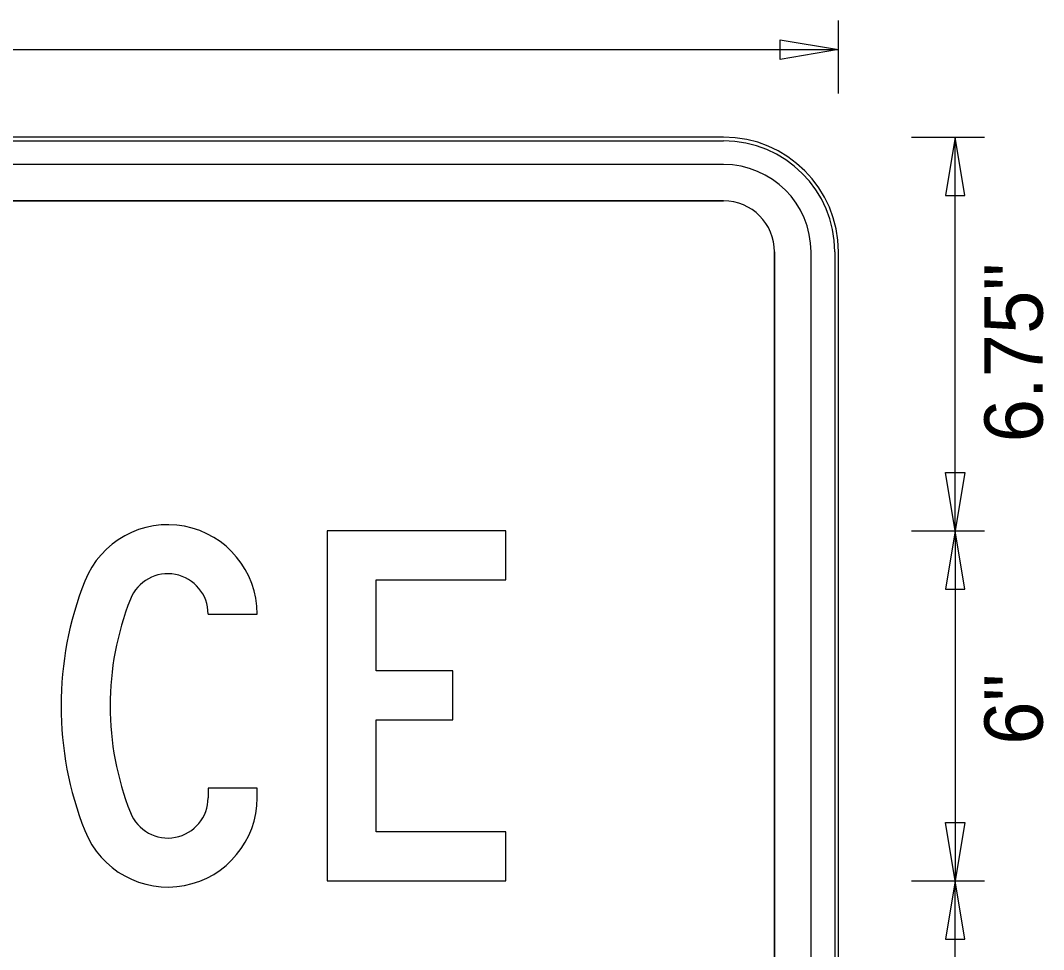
# Model space of a CAD drawing. Extents: x 1775472.9 to 1775494.7, y 1032415.7 to 1032420.8.
# Drawn here: x 1775475.339 to 1775477.092, y 1032418.237 to 1032419.83 of the extents above; entities that cross this region are included whole.
import ezdxf

# ---------------------------------------------------------------- set-up
doc = ezdxf.new("R2010")
doc.units = 0
for name, color, linetype in [('Default', 7, 'Continuous'), ('GSBWFILL', 7, 'Continuous'), ('GSCOLORFILL', 7, 'Continuous'), ('GSOUTLINE', 7, 'Continuous')]:
    doc.layers.add(name, color=color, linetype=linetype)

msp = doc.modelspace()

# ---------------------------------------------------------------- linework, layer by layer
at = {"layer": 'Default'}
for p, q in [((1775476.7401, 1032419.7052), (1775476.7401, 1032419.8302)), ((1775473.7401, 1032419.7802), (1775476.7401, 1032419.7802)), ((1775476.7401, 1032419.7052), (1775476.7401, 1032419.7052)), ((1775476.8651, 1032419.6302), (1775476.9901, 1032419.6302)), ((1775476.8651, 1032419.6302), (1775476.8651, 1032419.6302)), ((1775476.9401, 1032418.9552), (1775476.9401, 1032419.6302)), ((1775476.8651, 1032418.9552), (1775476.9901, 1032418.9552)), ((1775476.8651, 1032418.9552), (1775476.9901, 1032418.9552)), ((1775476.9401, 1032418.9552), (1775476.9401, 1032418.3552)), ((1775476.8651, 1032418.3552), (1775476.9901, 1032418.3552)), ((1775476.8651, 1032418.3552), (1775476.9901, 1032418.3552)), ((1775476.9401, 1032417.9052), (1775476.9401, 1032418.3552))]:
    msp.add_line(p, q, dxfattribs=at)
for points in [[(1775476.7401, 1032419.7802), (1775476.6401, 1032419.7635), (1775476.6401, 1032419.7969)], [(1775476.9401, 1032419.6302), (1775476.9234, 1032419.5302), (1775476.9568, 1032419.5302)], [(1775476.9401, 1032418.9552), (1775476.9234, 1032419.0552), (1775476.9568, 1032419.0552)], [(1775476.9401, 1032418.9552), (1775476.9234, 1032418.8552), (1775476.9568, 1032418.8552)], [(1775476.9401, 1032418.3552), (1775476.9234, 1032418.4552), (1775476.9568, 1032418.4552)], [(1775476.9401, 1032418.3552), (1775476.9234, 1032418.2552), (1775476.9568, 1032418.2552)]]:
    msp.add_lwpolyline(points, close=True, dxfattribs=at)
at = {"layer": 'GSBWFILL'}
for p, q in [((1775476.5432, 1032419.6302), (1775473.937, 1032419.6302)), ((1775476.5432, 1032419.5833), (1775473.937, 1032419.5833)), ((1775473.937, 1032419.5208), (1775476.5432, 1032419.5208)), ((1775476.6307, 1032419.4333), (1775476.6307, 1032416.8271)), ((1775476.6932, 1032416.8271), (1775476.6932, 1032419.4333)), ((1775476.7401, 1032416.8271), (1775476.7401, 1032419.4333)), ((1775475.6601, 1032418.8127), (1775475.7441, 1032418.8127))]:
    msp.add_line(p, q, dxfattribs=at)
msp.add_lwpolyline([(1775475.9481, 1032418.4392), (1775475.9481, 1032418.6312), (1775476.0795, 1032418.6312), (1775476.0795, 1032418.7152), (1775475.9481, 1032418.7152), (1775475.9481, 1032418.8712), (1775476.1701, 1032418.8712), (1775476.1701, 1032418.9552), (1775475.8641, 1032418.9552), (1775475.8641, 1032418.3552), (1775476.1701, 1032418.3552), (1775476.1701, 1032418.4392)], close=True, dxfattribs=at)
msp.add_lwpolyline([(1775475.7441, 1032418.4977), (1775475.7441, 1032418.5142), (1775475.6601, 1032418.5142), (1775475.6601, 1032418.4977)], dxfattribs=at)
for centre, radius, start, end in [((1775476.5432, 1032419.4333), 0.1969, 0, 90), ((1775476.5432, 1032419.4333), 0.15, 0, 90), ((1775476.5432, 1032419.4333), 0.0875, 0, 90), ((1775475.5911, 1032418.8127), 0.153, 0, 158.4314), ((1775475.9895, 1032418.6552), 0.5814, 158.4314, 201.5686), ((1775475.5911, 1032418.8127), 0.069, 0, 158.4314), ((1775475.9895, 1032418.6552), 0.4974, 158.4314, 201.5686), ((1775475.5911, 1032418.4977), 0.153, 201.5686, 0), ((1775475.5911, 1032418.4977), 0.069, 201.5686, 0)]:
    msp.add_arc(centre, radius, start, end, dxfattribs=at)
at = {"layer": 'GSCOLORFILL'}
for p, q in [((1775476.5432, 1032419.6302), (1775473.937, 1032419.6302)), ((1775476.5432, 1032419.6302), (1775473.937, 1032419.6302)), ((1775473.937, 1032419.6239), (1775476.5432, 1032419.6239)), ((1775476.5432, 1032419.5833), (1775473.937, 1032419.5833)), ((1775473.937, 1032419.5208), (1775476.5432, 1032419.5208)), ((1775476.6307, 1032419.4333), (1775476.6307, 1032416.8271)), ((1775476.6932, 1032416.8271), (1775476.6932, 1032419.4333)), ((1775476.7338, 1032419.4333), (1775476.7338, 1032416.8271)), ((1775476.7401, 1032416.8271), (1775476.7401, 1032419.4333)), ((1775476.7401, 1032416.8271), (1775476.7401, 1032419.4333)), ((1775475.6601, 1032418.8127), (1775475.7441, 1032418.8127))]:
    msp.add_line(p, q, dxfattribs=at)
msp.add_lwpolyline([(1775475.9481, 1032418.4392), (1775475.9481, 1032418.6312), (1775476.0795, 1032418.6312), (1775476.0795, 1032418.7152), (1775475.9481, 1032418.7152), (1775475.9481, 1032418.8712), (1775476.1701, 1032418.8712), (1775476.1701, 1032418.9552), (1775475.8641, 1032418.9552), (1775475.8641, 1032418.3552), (1775476.1701, 1032418.3552), (1775476.1701, 1032418.4392)], close=True, dxfattribs=at)
msp.add_lwpolyline([(1775475.7441, 1032418.4977), (1775475.7441, 1032418.5142), (1775475.6601, 1032418.5142), (1775475.6601, 1032418.4977)], dxfattribs=at)
for centre, radius, start, end in [((1775476.5432, 1032419.4333), 0.1969, 0, 90), ((1775476.5432, 1032419.4333), 0.1969, 0, 90), ((1775476.5432, 1032419.4333), 0.1906, 0, 90), ((1775476.5432, 1032419.4333), 0.15, 0, 90), ((1775476.5432, 1032419.4333), 0.0875, 0, 90), ((1775475.5911, 1032418.8127), 0.153, 0, 158.4314), ((1775475.9895, 1032418.6552), 0.5814, 158.4314, 201.5686), ((1775475.5911, 1032418.8127), 0.069, 0, 158.4314), ((1775475.9895, 1032418.6552), 0.4974, 158.4314, 201.5686), ((1775475.5911, 1032418.4977), 0.153, 201.5686, 0), ((1775475.5911, 1032418.4977), 0.069, 201.5686, 0)]:
    msp.add_arc(centre, radius, start, end, dxfattribs=at)
at = {"layer": 'GSOUTLINE'}
for p, q in [((1775476.5432, 1032419.6302), (1775473.937, 1032419.6302)), ((1775476.5432, 1032419.5833), (1775473.937, 1032419.5833)), ((1775476.5432, 1032419.5208), (1775473.937, 1032419.5208)), ((1775476.6307, 1032416.8271), (1775476.6307, 1032419.4333)), ((1775476.6932, 1032416.8271), (1775476.6932, 1032419.4333)), ((1775476.7401, 1032416.8271), (1775476.7401, 1032419.4333)), ((1775475.6601, 1032418.8127), (1775475.7441, 1032418.8127))]:
    msp.add_line(p, q, dxfattribs=at)
msp.add_lwpolyline([(1775475.9481, 1032418.4392), (1775475.9481, 1032418.6312), (1775476.0795, 1032418.6312), (1775476.0795, 1032418.7152), (1775475.9481, 1032418.7152), (1775475.9481, 1032418.8712), (1775476.1701, 1032418.8712), (1775476.1701, 1032418.9552), (1775475.8641, 1032418.9552), (1775475.8641, 1032418.3552), (1775476.1701, 1032418.3552), (1775476.1701, 1032418.4392)], close=True, dxfattribs=at)
msp.add_lwpolyline([(1775475.7441, 1032418.4977), (1775475.7441, 1032418.5142), (1775475.6601, 1032418.5142), (1775475.6601, 1032418.4977)], dxfattribs=at)
for centre, radius, start, end in [((1775476.5432, 1032419.4333), 0.1969, 0, 90), ((1775476.5432, 1032419.4333), 0.15, 0, 90), ((1775476.5432, 1032419.4333), 0.0875, 0, 90), ((1775475.5911, 1032418.8127), 0.153, 0, 158.4314), ((1775475.9895, 1032418.6552), 0.5814, 158.4314, 201.5686), ((1775475.5911, 1032418.8127), 0.069, 0, 158.4314), ((1775475.9895, 1032418.6552), 0.4974, 158.4314, 201.5686), ((1775475.5911, 1032418.4977), 0.153, 201.5686, 0), ((1775475.5911, 1032418.4977), 0.069, 201.5686, 0)]:
    msp.add_arc(centre, radius, start, end, dxfattribs=at)

# ---------------------------------------------------------------- texts
at = {"layer": 'Default'}
for s, p in [('6.75"', (1775477.0901, 1032419.1069)), ('6"', (1775477.0901, 1032418.5885))]:
    msp.add_text(s, height=0.1, rotation=90, dxfattribs=at).set_placement(p)

doc.saveas('drawing.dxf')
